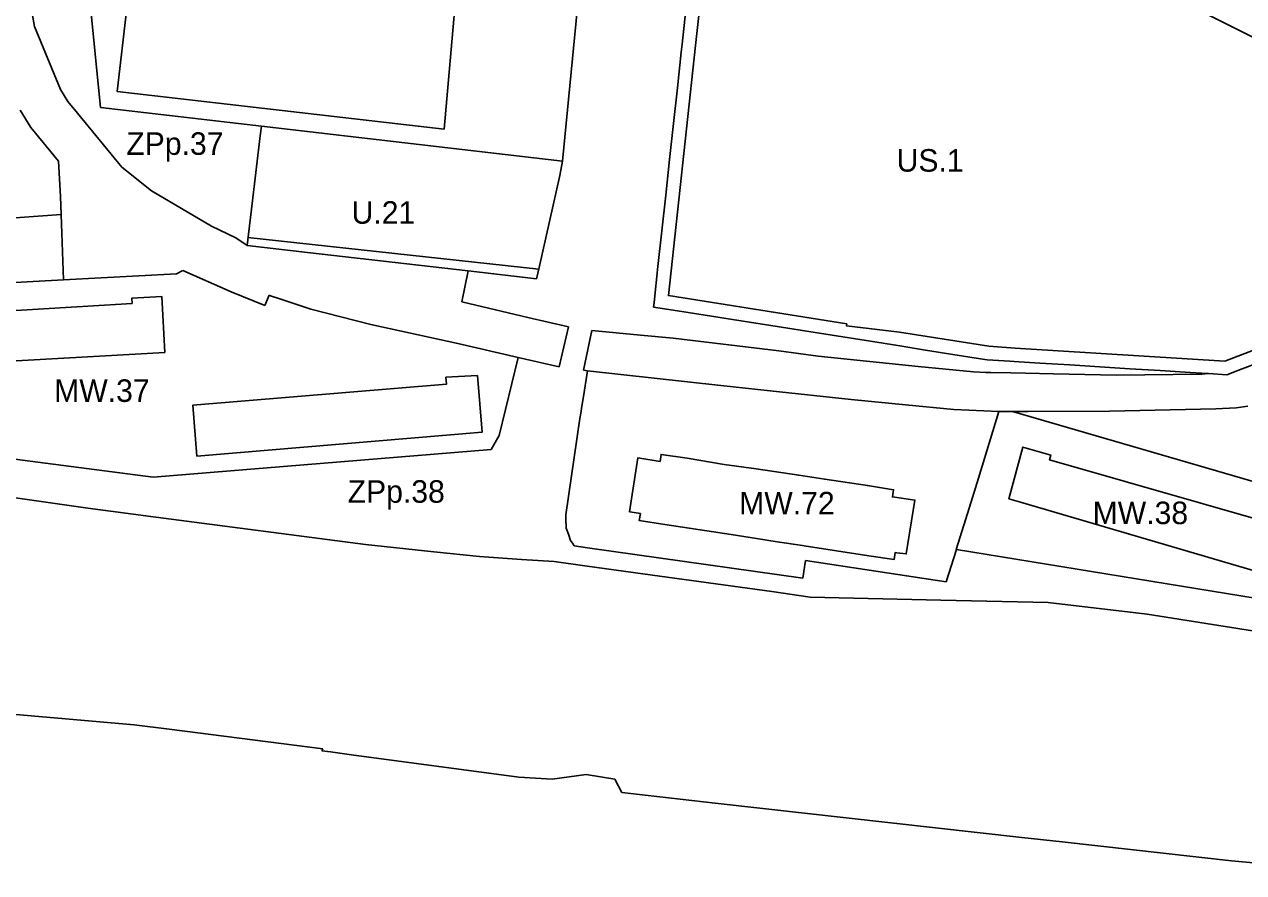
# Model space of a CAD drawing. Extents: x 7424434 to 7425898, y 5541432 to 5542659.
# Drawn here: x 7425250.1 to 7425520.4, y 5541437.3 to 5541625.5 of the extents above; entities that cross this region are included whole.
import ezdxf

# ---------------------------------------------------------------- set-up
doc = ezdxf.new("R2010")
doc.units = 0
for name, color, linetype in [('linie rozgraniczające', 7, 'Continuous'), ('nieprzekraczalne linie zabudowy', 7, 'Continuous'), ('obowiazujace linie zabudowy', 7, 'Continuous'), ('przeznaczenia terenów', 7, 'Continuous')]:
    doc.layers.add(name, color=color, linetype=linetype)

msp = doc.modelspace()

# ---------------------------------------------------------------- linework, layer by layer
at = {"layer": 'linie rozgraniczające'}
for p, q in [((7425377.25, 5541676.46), (7425369.41, 5541595.18)), ((7425266.99, 5541607.03), (7425264, 5541636.79)), ((7425252.31, 5541625.03), (7425250.96, 5541632.84)), ((7425396.09, 5541622.49), (7425396.61, 5541627.3)), ((7425258.13, 5541611.02), (7425252.31, 5541625.03)), ((7425395.74, 5541619.35), (7425395.93, 5541621.11)), ((7425395.93, 5541621.11), (7425396.09, 5541622.49)), ((7425394.88, 5541611.42), (7425395.74, 5541619.35)), ((7425259.71, 5541608.42), (7425258.13, 5541611.02)), ((7425394.01, 5541603.48), (7425394.88, 5541611.42)), ((7425261.88, 5541605.78), (7425259.71, 5541608.42)), ((7425302.69, 5541602.9), (7425266.99, 5541607.03)), ((7425251.53, 5541602.63), (7425249.19, 5541606.48)), ((7425271.68, 5541593.79), (7425261.88, 5541605.78)), ((7425257.65, 5541595.15), (7425251.53, 5541602.63)), ((7425302.36, 5541600.78), (7425302.69, 5541602.9)), ((7425302.69, 5541602.9), (7425369.41, 5541595.18)), ((7425393.15, 5541595.55), (7425394.01, 5541603.48)), ((7425300.46, 5541584.5), (7425302.36, 5541600.78)), ((7425258.14, 5541587.28), (7425257.65, 5541595.15)), ((7425278.27, 5541588.54), (7425271.68, 5541593.79)), ((7425369.41, 5541595.18), (7425368.83, 5541591.99)), ((7425392.29, 5541587.62), (7425393.15, 5541595.55)), ((7425368.83, 5541591.99), (7425364.21, 5541571.53)), ((7425291.61, 5541580.76), (7425278.27, 5541588.54)), ((7425258.28, 5541583.33), (7425258.14, 5541587.28)), ((7425391.43, 5541579.68), (7425392.29, 5541587.62)), ((7425242.41, 5541582.21), (7425258.28, 5541583.33)), ((7425258.28, 5541583.33), (7425258.79, 5541568.83)), ((7425299.8, 5541578.94), (7425300.46, 5541584.5)), ((7425296.97, 5541578.12), (7425291.61, 5541580.76)), ((7425299.51, 5541576.46), (7425296.97, 5541578.12)), ((7425299.51, 5541576.46), (7425299.8, 5541578.94)), ((7425390.56, 5541571.75), (7425391.43, 5541579.68)), ((7425312.9, 5541574.92), (7425299.51, 5541576.46)), ((7425348.51, 5541570.81), (7425312.9, 5541574.92)), ((7425389.7, 5541563.82), (7425390.56, 5541571.75)), ((7425283.82, 5541570.17), (7425258.79, 5541568.83)), ((7425285.26, 5541570.93), (7425283.82, 5541570.17)), ((7425295.98, 5541566.2), (7425285.26, 5541570.93)), ((7425348.51, 5541570.81), (7425347.06, 5541563.94)), ((7425363.65, 5541569.07), (7425348.51, 5541570.81)), ((7425364.21, 5541571.53), (7425363.65, 5541569.07)), ((7425258.79, 5541568.83), (7425232.84, 5541567.44)), ((7425303.4, 5541563.17), (7425295.98, 5541566.2)), ((7425304.35, 5541565.42), (7425303.4, 5541563.17)), ((7425304.68, 5541565.31), (7425304.35, 5541565.42)), ((7425306.7, 5541564.64), (7425304.68, 5541565.31)), ((7425313.61, 5541562.33), (7425306.7, 5541564.64)), ((7425347.06, 5541563.94), (7425361.72, 5541560.51)), ((7425389.59, 5541562.8), (7425389.7, 5541563.82)), ((7425326.94, 5541558.92), (7425313.61, 5541562.33)), ((7425394.91, 5541561.96), (7425389.59, 5541562.8)), ((7425401.02, 5541560.99), (7425394.91, 5541561.96)), ((7425407.12, 5541560.02), (7425401.02, 5541560.99)), ((7425346.22, 5541554.72), (7425326.94, 5541558.92)), ((7425361.72, 5541560.51), (7425370.75, 5541558.4)), ((7425370.75, 5541558.4), (7425368.68, 5541549.5)), ((7425413.23, 5541559.06), (7425407.12, 5541560.02)), ((7425419.33, 5541558.09), (7425413.23, 5541559.06)), ((7425374.07, 5541548.76), (7425375.92, 5541557.6)), ((7425375.92, 5541557.6), (7425386.67, 5541556.58)), ((7425386.67, 5541556.58), (7425393.95, 5541555.89)), ((7425393.95, 5541555.89), (7425417.35, 5541553.09)), ((7425425.44, 5541557.13), (7425419.33, 5541558.09)), ((7425431.54, 5541556.16), (7425425.44, 5541557.13)), ((7425437.65, 5541555.19), (7425431.54, 5541556.16)), ((7425359.59, 5541551.61), (7425346.22, 5541554.72)), ((7425417.35, 5541553.09), (7425426.05, 5541551.9)), ((7425443.75, 5541554.23), (7425437.65, 5541555.19)), ((7425449.86, 5541553.26), (7425443.75, 5541554.23)), ((7425455.96, 5541552.29), (7425449.86, 5541553.26)), ((7425355.36, 5541534.29), (7425359.59, 5541551.61)), ((7425368.68, 5541549.5), (7425359.59, 5541551.61)), ((7425426.05, 5541551.9), (7425448.23, 5541549.59)), ((7425462.06, 5541551.33), (7425455.96, 5541552.29)), ((7425463.56, 5541551.09), (7425462.06, 5541551.33)), ((7425468.58, 5541550.77), (7425463.56, 5541551.09)), ((7425469.55, 5541550.71), (7425468.58, 5541550.77)), ((7425475.24, 5541550.36), (7425469.55, 5541550.71)), ((7425481.89, 5541549.94), (7425475.24, 5541550.36)), ((7425525.56, 5541551.18), (7425518.53, 5541548.49)), ((7425374.97, 5541548.66), (7425374.07, 5541548.76)), ((7425374.13, 5541543.37), (7425374.97, 5541548.66)), ((7425404.51, 5541545.42), (7425374.97, 5541548.66)), ((7425448.23, 5541549.59), (7425460.54, 5541548.44)), ((7425460.54, 5541548.44), (7425463.28, 5541548.24)), ((7425463.28, 5541548.24), (7425464.36, 5541548.24)), ((7425464.36, 5541548.24), (7425468.77, 5541548.17)), ((7425468.77, 5541548.17), (7425472.06, 5541548.12)), ((7425472.06, 5541548.12), (7425478.25, 5541547.97)), ((7425478.25, 5541547.97), (7425492.14, 5541547.69)), ((7425488.55, 5541549.53), (7425481.89, 5541549.94)), ((7425495.21, 5541549.11), (7425488.55, 5541549.53)), ((7425492.14, 5541547.69), (7425511.14, 5541547.87)), ((7425501.87, 5541548.7), (7425495.21, 5541549.11)), ((7425508.52, 5541548.29), (7425501.87, 5541548.7)), ((7425511.16, 5541548.12), (7425508.52, 5541548.29)), ((7425511.14, 5541547.87), (7425512.59, 5541548.03)), ((7425512.59, 5541548.03), (7425511.16, 5541548.12)), ((7425516.67, 5541547.78), (7425512.59, 5541548.03)), ((7425518.4, 5541548.44), (7425516.67, 5541547.78)), ((7425518.53, 5541548.49), (7425518.4, 5541548.44)), ((7425415.45, 5541544.22), (7425404.51, 5541545.42)), ((7425373.65, 5541540.39), (7425374.13, 5541543.37)), ((7425433.39, 5541542.26), (7425415.45, 5541544.22)), ((7425445.48, 5541541.1), (7425433.39, 5541542.26)), ((7425373.28, 5541538.04), (7425373.53, 5541539.63)), ((7425373.53, 5541539.63), (7425373.65, 5541540.39)), ((7425456.19, 5541540.07), (7425445.48, 5541541.1)), ((7425466.14, 5541539.64), (7425456.19, 5541540.07)), ((7425461.62, 5541524.87), (7425466.14, 5541539.64)), ((7425469.17, 5541539.63), (7425466.14, 5541539.64)), ((7425537.07, 5541519.86), (7425469.17, 5541539.63)), ((7425469.17, 5541539.63), (7425472.63, 5541539.62)), ((7425472.63, 5541539.62), (7425490.7, 5541539.66)), ((7425490.7, 5541539.66), (7425514.24, 5541540.19)), ((7425514.24, 5541540.19), (7425518.78, 5541540.45)), ((7425518.78, 5541540.45), (7425521.37, 5541540.81)), ((7425186.01, 5541537.05), (7425278.62, 5541525.09)), ((7425370.13, 5541516.71), (7425373.28, 5541538.04)), ((7425353.6, 5541531.16), (7425355.36, 5541534.29)), ((7425278.62, 5541525.09), (7425353.6, 5541531.16)), ((7425459.64, 5541518.42), (7425461.62, 5541524.87)), ((7425238.22, 5541521.9), (7425264.19, 5541518.15)), ((7425264.19, 5541518.15), (7425279.22, 5541516.2)), ((7425456.71, 5541509.01), (7425459.64, 5541518.42)), ((7425279.22, 5541516.2), (7425325.76, 5541510.14)), ((7425370.16, 5541515.88), (7425370.13, 5541516.71)), ((7425370.25, 5541513.74), (7425370.16, 5541515.88)), ((7425370.71, 5541512.38), (7425370.25, 5541513.74)), ((7425371.17, 5541511.02), (7425370.71, 5541512.38)), ((7425325.76, 5541510.14), (7425340.88, 5541508.53)), ((7425371.59, 5541510.42), (7425371.17, 5541511.02)), ((7425372, 5541509.82), (7425371.59, 5541510.42)), ((7425374.91, 5541509.41), (7425372, 5541509.82)), ((7425340.88, 5541508.53), (7425350.99, 5541507.46)), ((7425350.99, 5541507.46), (7425360.32, 5541506.83)), ((7425360.32, 5541506.83), (7425367.56, 5541506.33)), ((7425422.7, 5541502.69), (7425374.91, 5541509.41)), ((7425456.75, 5541509), (7425454.47, 5541501.83)), ((7425456.71, 5541509.01), (7425456.75, 5541509)), ((7425456.75, 5541509), (7425536.63, 5541495.96)), ((7425367.56, 5541506.33), (7425374.35, 5541505.4)), ((7425374.35, 5541505.4), (7425385.62, 5541503.85)), ((7425423.24, 5541506.55), (7425422.7, 5541502.69)), ((7425454.47, 5541501.83), (7425423.24, 5541506.55)), ((7425385.62, 5541503.85), (7425415.78, 5541499.71)), ((7425415.78, 5541499.71), (7425424.31, 5541498.43)), ((7425424.31, 5541498.43), (7425453.31, 5541497.79)), ((7425453.31, 5541497.79), (7425477.1, 5541497.27)), ((7425477.1, 5541497.27), (7425499.02, 5541494.66)), ((7425499.02, 5541494.66), (7425545.68, 5541487.28)), ((7425274.44, 5541470.13), (7425238.89, 5541473.19)), ((7425282.21, 5541469.14), (7425274.44, 5541470.13)), ((7425316.27, 5541464.8), (7425282.21, 5541469.14)), ((7425316.03, 5541464.36), (7425316.27, 5541464.8)), ((7425317.93, 5541464.11), (7425316.03, 5541464.36)), ((7425322.65, 5541463.48), (7425317.93, 5541464.11)), ((7425359.73, 5541458.52), (7425322.65, 5541463.48)), ((7425367.1, 5541458.08), (7425359.73, 5541458.52)), ((7425374.67, 5541459.09), (7425367.1, 5541458.08)), ((7425381.02, 5541458.04), (7425374.67, 5541459.09)), ((7425382.54, 5541455.1), (7425381.02, 5541458.04)), ((7425403.25, 5541452.74), (7425382.54, 5541455.1)), ((7425471.25, 5541445.16), (7425403.25, 5541452.74)), ((7425480.19, 5541444.16), (7425471.25, 5541445.16)), ((7425517.75, 5541439.97), (7425480.19, 5541444.16)), ((7425545.85, 5541437.34), (7425517.75, 5541439.97))]:
    msp.add_line(p, q, dxfattribs=at)
at = {"layer": 'nieprzekraczalne linie zabudowy'}
msp.add_line((7425299.66, 5541578.22), (7425364.17, 5541571.16), dxfattribs=at)
for points in [[(7425343.14, 5541602.25), (7425348.81, 5541666.31), (7425290.29, 5541671.61), (7425277.07, 5541666.14), (7425270.65, 5541610.63)], [(7425516.21, 5541550.81), (7425539.76, 5541559.82), (7425542.87, 5541562.42), (7425566.11, 5541581.87), (7425568.69, 5541610.4), (7425544.11, 5541613.7), (7425524.39, 5541621.67), (7425514.3, 5541626.75), (7425462.65, 5541652.8), (7425423.35, 5541666), (7425404.27, 5541669.87), (7425401.75, 5541646.75), (7425399.07, 5541622.15), (7425398.91, 5541620.78), (7425392.88, 5541565.32), (7425432.43, 5541559.06), (7425432.38, 5541558.61), (7425444.12, 5541557.2), (7425463.89, 5541554.08), (7425469.74, 5541553.7)], [(7425384.22, 5541517.35), (7425384.29, 5541517.34), (7425386.26, 5541517.05), (7425386.67, 5541516.99), (7425386.42, 5541515.41), (7425392.07, 5541514.55), (7425392.07, 5541514.55), (7425392.07, 5541514.55), (7425406.81, 5541512.32), (7425406.81, 5541512.32), (7425406.81, 5541512.32), (7425406.81, 5541512.32), (7425412.4, 5541511.47), (7425412.4, 5541511.47), (7425412.4, 5541511.47), (7425417.02, 5541510.74), (7425417.02, 5541510.74), (7425417.02, 5541510.74), (7425422.59, 5541509.9), (7425422.97, 5541509.84), (7425422.97, 5541509.84), (7425437.3, 5541507.61), (7425437.3, 5541507.61), (7425437.3, 5541507.61), (7425442.93, 5541506.79), (7425443.16, 5541508.36), (7425443.55, 5541508.31), (7425445.61, 5541508.02), (7425447.54, 5541519.98), (7425442.55, 5541520.69), (7425442.8, 5541522.27), (7425437.01, 5541523.18), (7425437.01, 5541523.18), (7425437.01, 5541523.18), (7425427.55, 5541524.59), (7425427.55, 5541524.59), (7425427.55, 5541524.59), (7425421.77, 5541525.48), (7425421.77, 5541525.48), (7425412.31, 5541526.94), (7425412.31, 5541526.94), (7425405.26, 5541527.88), (7425397.04, 5541529.25), (7425397.04, 5541529.25), (7425397.04, 5541529.25), (7425397.04, 5541529.25), (7425397.04, 5541529.25), (7425391.26, 5541530.12), (7425391.02, 5541528.54), (7425386.08, 5541529.31)]]:
    msp.add_lwpolyline(points, close=True, dxfattribs=at)
at = {"layer": 'obowiazujace linie zabudowy'}
for points in [[(7425188.91, 5541547.52), (7425281.23, 5541552.74), (7425280.57, 5541565.14), (7425273.91, 5541564.73), (7425273.98, 5541563.61), (7425188.07, 5541558.37)], [(7425288.3, 5541529.75), (7425351.6, 5541535.07), (7425350.55, 5541547.58), (7425343.57, 5541547.22), (7425343.71, 5541545.72), (7425287.48, 5541541.05)], [(7425470.94, 5541519.51), (7425541.67, 5541498.71), (7425545.01, 5541509.52), (7425477.34, 5541528.93), (7425477.64, 5541529.96), (7425471.45, 5541531.73), (7425468.39, 5541520.26)]]:
    msp.add_lwpolyline(points, close=True, dxfattribs=at)

# ---------------------------------------------------------------- texts
at = {"layer": 'przeznaczenia terenów'}
for s, p in [('ZPp.37', (7425272.69, 5541596.55)), ('US.1', (7425443.47, 5541592.82)), ('U.21', (7425322.64, 5541581.27)), ('MW.37', (7425256.7, 5541541.75)), ('ZPp.38', (7425321.76, 5541519.38)), ('MW.72', (7425408.57, 5541516.79)), ('MW.38', (7425486.93, 5541514.64))]:
    msp.add_text(s, height=5, dxfattribs=at).set_placement(p)

doc.saveas('drawing.dxf')
